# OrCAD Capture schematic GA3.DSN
size A
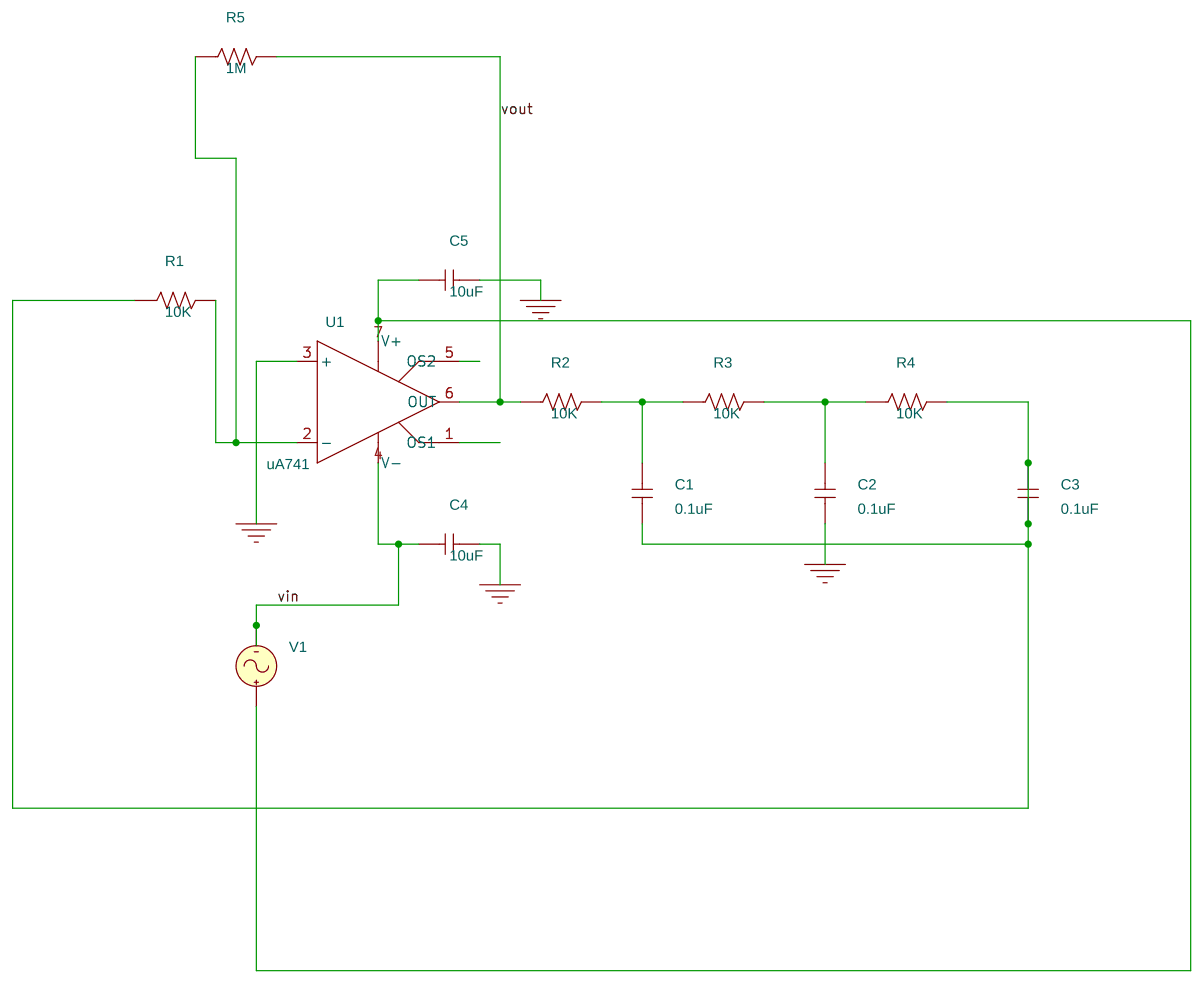
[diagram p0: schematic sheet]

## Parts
C1  0.1uF  [RAD/CK05]
C2  0.1uF  [RAD/CK05]
C3  0.1uF  [RAD/CK05]
C4  10uF  [RAD/CK05]
C5  10uF  [RAD/CK05]
R1  10K  [AX/RC05]
R2  10K  [AX/RC05]
R3  10K  [AX/RC05]
R4  10K  [AX/RC05]
R5  1M  [AX/RC05]
U1  uA741  [DIP.100/8/W.300/L.450]
V1  VAC

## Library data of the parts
C1-C3 = C
C4 C5 = c
R1-R5 = R
U1 = uA741
V1 = VAC

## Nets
vin: C4.1 U1.4(V-) V1.2(-)
0: C2.1 C4.2 C5.2 U1.3(+)
vout: R2.1 R5.2 U1.6(OUT)
N02408: C5.1 U1.7(V+) V1.1(+)
N02454: R1.2 R5.1 U1.2(-)
N02735: C1.2 R2.2 R3.1
N02739: C2.2 R3.2 R4.1
N02743: C1.1 C3.1 C3.2 R1.1 R4.2

Not connected (* = marked no-connect by the designer): U1 1(OS1) 5(OS2)
